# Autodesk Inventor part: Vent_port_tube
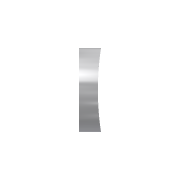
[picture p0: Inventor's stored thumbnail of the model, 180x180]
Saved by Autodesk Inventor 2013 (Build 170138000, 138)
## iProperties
Created: 2012-05
Part Number: Vent_port_tube
Material: Stainless Steel, 316
Document SubType Name: Modeling
Designer: ssc
Mass: 946.545 g
Surface Area: 801.814 cm^2
Volume: 119.062 cm^3
Density: 7.95 g/cm^3
Author: ssc
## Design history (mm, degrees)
sketch "Sketch1"
  geometry: C1 r 70.65 at (0, 0); C2 r 67.246 at (0, 0)
  constraints: 2 centre point, 1 coincident, 1 other
  dimensions: "d0" = 141.3002 diameter of C1; "d1" = 3.4036 radial gap between concentric circles of C2 C1
extrude "Extrusion1" new body sketch "Sketch1" distance "d2" = 152.4; taper "d3" = 0 deg
sketch "Sketch2"
  geometry: L1 (-70.65, 152.4)-(70.65, 152.4) reference; L2 (-70.65, 0)-(70.65, 0) reference; L3 (0, -198.12)-(0, 1188.72) reference; C1 r 476.25 at (0, 508)
  constraints: 1 centre point
  dimensions: "d4" = 0 distance from line of L3 C1.centre; "d5" = 952.5 diameter of C1; "d6" = 508 distance from line of C1.centre L2
extrude "Extrusion2" cut sketch "Sketch2" stored distance "d7" = 152.4; taper "d8" = 0 deg
body "Solid1"
node "Projected Loop1"
